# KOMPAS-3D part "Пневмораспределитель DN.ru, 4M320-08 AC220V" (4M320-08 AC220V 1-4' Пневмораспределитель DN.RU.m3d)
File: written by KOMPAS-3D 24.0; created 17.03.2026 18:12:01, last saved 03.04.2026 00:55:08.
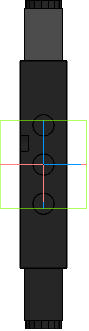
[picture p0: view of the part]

Document properties: Автор: R2D2; Полное имя файла: E:\Работа\Зайцев\Аксессуары для пневмоприводов\Пневмораспределители DN.ru\4M320 AC220V Пневмораспределитель DN.RU\4M320-08 AC220V Пневмораспределитель DN.RU\исходные материалы\4M320-08 AC220V 1-4' Пневмораспределитель DN.RU.m3d

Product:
- Body: Тело 1  | qty 1
    Масса: 1.613525
- Body: Тело 3  | qty 1
    Масса: 1.613525
- Part/product: Пневмораспределитель DN.ru  | designation 4M320-08 AC220V
    Масса: 1.2
    Раздел спецификации: Прочие изделия
    Примечание: D290-00364

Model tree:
1. Эскиз:1
2. Элемент выдавливания:1
     Расстояние 1 = 118.8
3. Эскиз:2  (with: Грань.Элемент выдавливания:1)
4. Элемент выдавливания:2
     Расстояние 2 = 1.4
5. Эскиз:3  (with: Грань.Элемент выдавливания:1, Ребро.Элемент выдавливания:2)
6. Элемент выдавливания:3
     Расстояние 2 = 27
7. Эскиз:4  (with: Грань.Элемент выдавливания:1, Ребро.Элемент выдавливания:1)
8. Элемент выдавливания:4
     Расстояние 1 = 30
9. Эскиз:5  (with: Грань.Элемент выдавливания:4, Ребро.Элемент выдавливания:4)
10. Элемент выдавливания:5
     Расстояние 1 = 27
11. Эскиз:6  (with: Грань.Элемент выдавливания:4)
12. Элемент выдавливания:6
     Расстояние 1 = 5
13. Эскиз:7  (with: Грань.Элемент выдавливания:5)
14. Элемент выдавливания:7
     Расстояние 1 = 14
15. Эскиз:8  (with: Грань.Элемент выдавливания:7, Ребро.Элемент выдавливания:7)
16. Элемент выдавливания:8
     Расстояние 1 = 5
17. Эскиз:9  (with: Грань.Элемент выдавливания:1, Ребро.Элемент выдавливания:4)
18. Элемент выдавливания:9
     Расстояние 1 = 2.4
19. Эскиз:12  (with: Грань.Элемент выдавливания:9, Ребро.Элемент выдавливания:9)
20. Элемент выдавливания:12
     Расстояние 2 = 1
21. Эскиз:10  (with: Грань.Элемент выдавливания:1)
22. Элемент выдавливания:10
     Расстояние 2 = 5
23. пазы  (with: Грань.Элемент выдавливания:1, Ребро.Элемент выдавливания:3)
24. Элемент выдавливания:11
     Расстояние 2 = 5
25. Зеркальный массив:2
26. Экземпляр ( 1 )
27. Экземпляр ( 2 )  (with: Элемент выдавливания:4, Элемент выдавливания:6, Элемент выдавливания:5, Элемент выдавливания:7, Элемент выдавливания:8, Элемент выдавливания:9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)

Expressions: 4M320-08 AC220V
